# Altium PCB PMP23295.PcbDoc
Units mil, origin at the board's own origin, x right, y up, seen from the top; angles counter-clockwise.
Board outline 3149.61 x 1368.11 mil, 2 copper layers (Top Layer, Bottom Layer), stack 62 mil thick; 35 components, 23 nets, 88 pads, 2 vias.
Unrouted connection lines stored in the file: 14.
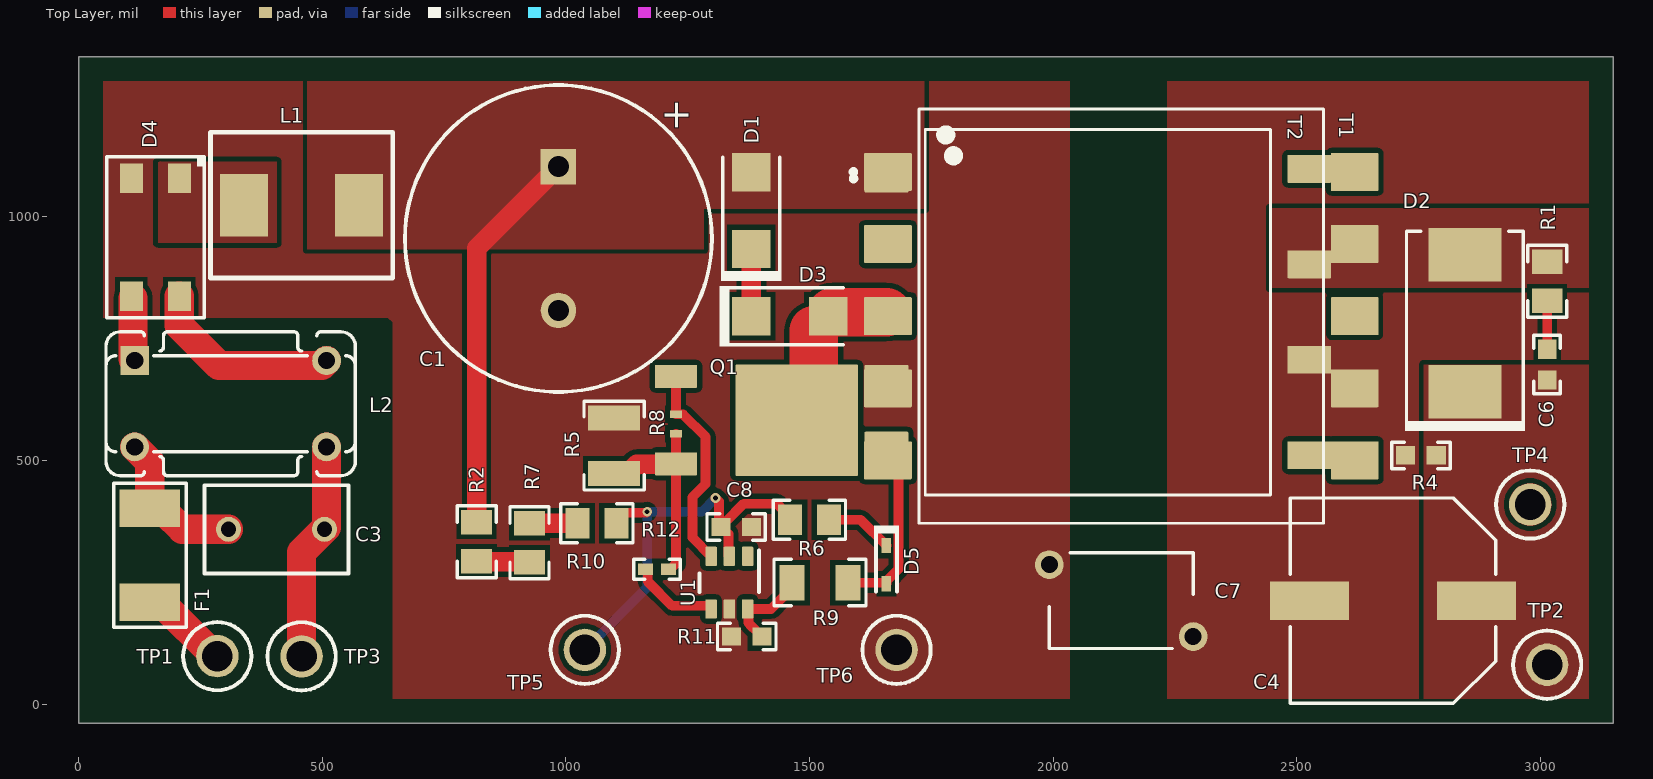
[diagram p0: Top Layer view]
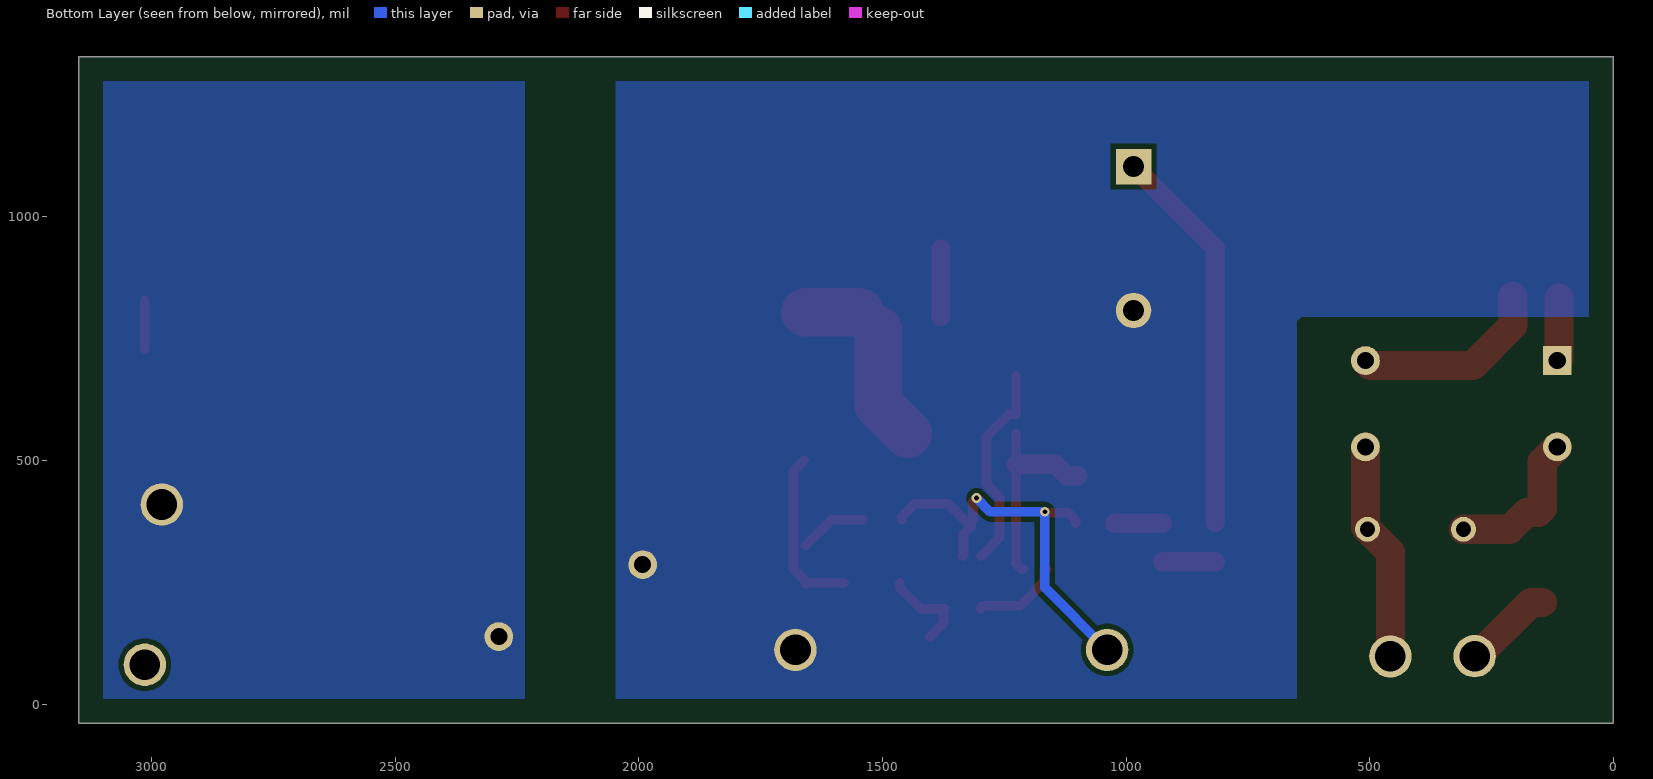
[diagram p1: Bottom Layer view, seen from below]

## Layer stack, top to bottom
Top Solder: solder mask 0.4, Solder Resist, Dk 3.5
Top Layer: signal copper 1.4
Dielectric1: core 59.2, FR-4 High Tg, Dk 4.8
Bottom Layer: signal copper 1.4
Bottom Solder: solder mask 0.4, Solder Resist, Dk 3.5

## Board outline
0,-39.37 3149.61,-39.37 3149.61,1328.74 0,1328.74

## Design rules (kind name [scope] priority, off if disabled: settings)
AcuteAngle [All] p1: minimum=4.50000000000000E+0001 checktracksonly=TRUE
AssemblyTestPointUsage [All] p1: valid=2
BoardOutlineClearance BoardOutlineClearance_MountingHoles [OnCopper and InComponentClass('Mounting Holes')] p1: gap=39.37 ignorepadtopadclearanceinfootprint=FALSE
BoardOutlineClearance BoardOutlineClearance_Poly [OnCopper and IsPoly] p2: gap=50 ignorepadtopadclearanceinfootprint=FALSE
BoardOutlineClearance [OnCopper and Not InComponentClass('Logo') and not InComponentClass('FiducialMark') and not InRegion(1000,500,4000,800) and not InPoly] p3: gap=75 ignorepadtopadclearanceinfootprint=FALSE
Clearance Clearance_Keepouts [((IsTrack Or IsArc) And Not InPoly) And IsFree and IsKeepOut vs ((IsTrack Or IsArc) And Not InPoly) And IsFree and IsKeepOut] p1: gap=0 ignorepadtopadclearanceinfootprint=FALSE
Clearance Clearance_Poly [InPolygon] p2: gap=10 ignorepadtopadclearanceinfootprint=TRUE
Clearance Clearance_FiducialMark [IsKeepOut and InComponentClass('FiducialMark') vs IsPad and InComponentClass('FiducialMark')] p3: gap=0 ignorepadtopadclearanceinfootprint=FALSE
Clearance [All] p4: gap=5 ignorepadtopadclearanceinfootprint=TRUE
ComponentClearance ComponentClearance_2 [InComponent('NT*')] p1: gap=0 collisioncheckmode=3 verticalgap=0 showdistances=FALSE
ComponentClearance ComponentClearance_MountingHoles_FiducialMarks [InComponentClass('Mounting Holes') vs InComponentClass('FiducialMark')] p2: gap=10 collisioncheckmode=3 verticalgap=10 showdistances=FALSE
ComponentClearance ComponentClearance_Shunt [InComponentClass('Header') vs InComponentClass('Shunt')] p3: gap=0 collisioncheckmode=3 verticalgap=0 showdistances=FALSE
ComponentClearance ComponentClearance_Logo [InComponentClass('Logo')] p4: gap=10 collisioncheckmode=3 verticalgap=10 showdistances=FALSE
ComponentClearance ComponentClearance_ScrewToNut [(HasFootprint('NY PMS 440 0025 PH')) vs (HasFootprint('Keystone_1902C'))] p5: gap=5 collisioncheckmode=3 verticalgap=10 showdistances=FALSE
ComponentClearance ComponentClearance_MountingHoles [InComponentClass('Mounting Holes')] p6: gap=10 collisioncheckmode=3 verticalgap=100000 showdistances=FALSE
ComponentClearance ComponentClearance_SmallPassives [HasFootprint('0201*') or HasFootprint('0402*') or HasFootprint('0508') or HasFootprint('0603*') or HasFootprint('0612') or HasFootprint('0805*') or HasFootprint('0815*') or HasFootprint('0830*') or HasFootprint('1206*') or HasFootprint('1210*') or HasFootprint('1808*') or HasFootprint('1812*') or HasFootprint('1825*') or HasFootprint('2010*') or HasFootprint('2220*') or HasFootprint('2225*') or HasFootprint('2512*') or HasFootprint('2728*') or HasFootprint('3518*') vs HasFootprint('0201*') or HasFootprint('0402*') or HasFootprint('0508') or HasFootprint('0603*') or HasFootprint('0612') or HasFootprint('0805*') or HasFootprint('0815*') or HasFootprint('0830*') or HasFootprint('1206*') or HasFootprint('1210*') or HasFootprint('1808*') or HasFootprint('1812*') or HasFootprint('1825*') or HasFootprint('2010*') or HasFootprint('2220*') or HasFootprint('2225*') or HasFootprint('2512*') or HasFootprint('2728*') or HasFootprint('3518*')] p7: gap=10 collisioncheckmode=3 verticalgap=10 showdistances=FALSE
ComponentClearance ComponentClearance_THtoSMT [IsThruComponent vs IsSMTComponent] p8: gap=10 collisioncheckmode=3 verticalgap=30 showdistances=FALSE
ComponentClearance ComponentClearance_THtoTH [IsThruComponent vs IsThruComponent] p9: gap=10 collisioncheckmode=3 verticalgap=30 showdistances=FALSE
ComponentClearance [All] p10: gap=10 collisioncheckmode=3 verticalgap=10 showdistances=FALSE
DiffPairsRouting [All] p1: maxlimit=100 minlimit=10 mostfreqgap=10 toplayer_minwidth=6 toplayer_maxwidth=15 toplayer_prefwidth=6 bottomlayer_minwidth=6 bottomlayer_maxwidth=15 bottomlayer_prefwidth=6 maxuncoupledlength=1000
FabricationTestPointUsage TestPointUsage [All] p1: valid=2 allowmultiple=FALSE
FabricationTestpoint Testpoint [All] p1: side=3 testpointundercomponent=TRUE minsize=40 maxsize=100 preferedsize=60 minholesize=0 maxholesize=40 preferedholesize=32 testpointgrid=1 allowsidetop=TRUE allowsidebottom=TRUE usegrid=TRUE gridtolerance=0.01
FanoutControl Fanout_LCC [IsLCC] p1: bgadir=Out bgaviamode=Centered fanoutstyle=Auto fanoutdirection=Alternating viagrid=1 // Fanout_LCC (Default Rule)
FanoutControl Fanout_BGA [IsBGA] p2: bgadir=Out bgaviamode=Centered fanoutstyle=Auto fanoutdirection=Alternating viagrid=1 // Fanout_BGA (Default Rule)
FanoutControl Fanout_Default [All] p4: bgadir=Out bgaviamode=Centered fanoutstyle=Auto fanoutdirection=Alternating viagrid=1 // Fanout_Default (Default Rule)
FanoutControl Fanout_Small [(CompPinCount < 5)] p5: bgadir=Out bgaviamode=Centered fanoutstyle=Auto fanoutdirection=OutThenIn viagrid=1 // Fanout_Small (Default Rule)
Height [All] p1: minheight=0 maxheight=1100 prefheight=500
HoleSize [All] p1: absolutevalues=TRUE maxlimit=270 minlimit=7.87 maxpercent=80.000 minpercent=20.000
HoleToHoleClearance [All] p1: gap=5 allowstackedmicrovias=TRUE
MinimumAnnularRing MinimumAnnularRing_ThermalPadVias [IsVia and InAnyComponent] p1: minimumring=4
MinimumAnnularRing [All] p2: minimumring=4
MinimumSolderMaskSliver MinimumSolderMaskSliver_Logo [InComponentClass('Logo') vs InComponentClass('Logo')] p1: minsoldermaskwidth=0.7
MinimumSolderMaskSliver [All] p2: minsoldermaskwidth=1.5
PlaneClearance [All] p1: clearance=5
PlaneConnect [All] p1: planeconnectstyle=Relief reliefexpansion=10 reliefentries=4 reliefconductorwidth=10 reliefairgap=10
PolygonConnect [All] p1: connectstyle=Direct reliefconductorwidth=10 reliefentries=4 polygonreliefangle="90 Angle" airgapwidth=10
RoutingVias ThermalPadVias [IsVia and InAnyComponent] p1: holewidth=7.87 width=19.68 viastyle="Through Hole" minholewidth=7.87 minwidth=19.68 maxholewidth=12.99 maxwidth=23.62
RoutingVias [All] p2: holewidth=10 width=18 viastyle="Through Hole" minholewidth=4 minwidth=15 maxholewidth=40 maxwidth=64
SMDEntry [All] p1 off: side=TRUE corner=TRUE anyangle=FALSE
SMDToCorner [All] p1 off: distance=50000
SilkToBoardRegionClearance [Not ((IsComment or IsDesignator) And (Hide <> 'False')) and not InRegion(1000,500,4000,800)] p1:
SilkToSilkClearance SilkToSilkClearance_Pb-FreeLogo [(HasFootprint('Pb-Free_Overlay_Medium') OR HasFootprint('Pb-Free_Overlay_Small')) vs (HasFootprint('Pb-Free_Overlay_Medium') OR HasFootprint('Pb-Free_Overlay_Small'))] p1: silktosilkclearance=0
SilkToSilkClearance [All] p2: silktosilkclearance=0
SilkToSolderMaskClearance SilkToComponentPadClearance [(IsPad or IsFill or IsRegion) and InAnycomponent] p1: minsilkscreentomaskgap=3 clearancetoexposedcopper=TRUE
SilkToSolderMaskClearance "Silk to Solder Mask Opening" [All] p2: minsilkscreentomaskgap=3.94 clearancetoexposedcopper=FALSE
SolderMaskExpansion [All] p1: expansion=4 istentingtop=FALSE
UnRoutedNet [All] p1: checkbadconnections=TRUE
Width [All] p1: maxlimit=100 minlimit=5 preferedwidth=10 checkconnectedcopper=TRUE
11 further rules are at their usual default settings.

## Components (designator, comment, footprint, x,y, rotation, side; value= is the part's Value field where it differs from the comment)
C1 "EEUED2D151" CAPPR7.5-16x25 984.54,955.63 r270 top value=150uF
C3 "R82IC3100DQ60J" R82_720x450x950 405.9,358.83 r0 top value=0.1uF
C4 "EEE-FC1H101P" SM_RADIAL_G 2697.56,212.41 r180 top value=100uF
C6 "06031C102MAT2A" 0603 3014.01,696.77 r90 top value=1000pF
C7 "VY2471K29Y5SS63V7" VY2_750x500 2139.82,212.42 r180 top value=470pF
C8 "C1608X5R1H105K080AB" 0603 1349.44,363.7 r0 top value=1uF
D1 "SMAJ150A" SMA 1380.63,1012.84 r90 top value=150V
D2 "CDBC5200-HF" SMC 2845.19,781.77 r90 top value=200V
D3 "US1G-13-F" SMA 1459.37,796.3 r0 top value=400V
D4 "HD02-T" MiniDIP 157.2,958.27 r270 top value=200V
D5 "1N4148WT" Fairchild_SOD-523F 1657.72,286.24 r270 top value=75V
F1 "045201.5MRL" SloBlo452 145.54,305.48 r270 top
L1 "DR74-101-R" DR74 457.4,1024.21 r0 top value=100uH
L2 "744821201" WE-CMB_XS 311.73,616.51 r0 top value=1mH
Q1 "SPD03N60S5XT" FP-IPD50R2K0CEAUMA1_PG-TO252-3-MFG 1427.53,582.79 r270 top
R1 "RP73PF2A1K0BTDF" 0805_HV 3014.01,868.22 r270 top value=1.00k
R2 "CRCW08051M00JNEA" 0805_HV 816.54,333.01 r90 top value=1.0Meg
R4 "RCA06031K00JNEA" 0603 2754.95,510.61 r0 top value=1.0k
R5 "MCR25JZHFLR150" 1210 1098.77,530.61 r270 top value=0.15
R6 "RC0805FR-0710RL" 0805_HV 1499.82,378.47 r180 top value=10.0
R7 "CRCW08051M00JNEA" 0805_HV 925.2,331.3 r270 top value=1.0Meg
R8 "MCS0402MD1002BE100" 0402S 1225.76,574.91 r90 top value=10.0k
R9 "ERJ-8ENF4873V" 1206 1521.42,249.32 r0 top value=487k
R10 "CRCW0402110RFKED" 0402 1186.87,277.06 r0 top value=110
R11 "RT0603BRD07182KL" 0603 1371.09,138.52 r0 top value=182k
R12 "CRCW08051M00JNEA" 0805_HV 1063.7,371.3 r180 top value=1.0Meg
T1 "RLTI-1453" FP-RLTI-1453_SMT10_0IN85_0IN80-MFG 2139.82,796.3 r0 top
T2 "RLTI-1452" FP-RLTI-1452_SMT9_0IN75_0IN93-MFG 2091.72,804.61 r0 top
TP1 "5012" Keystone5012 284.35,98.43 r0 top
TP2 "5010" Keystone5010 3014.01,80.82 r90 top
TP3 "5011" Keystone5011 457.4,97.98 r0 top
TP4 "5011" Keystone5011 2979.21,409.64 r90 top
TP5 "5010" Keystone5010 1038.67,111.32 r180 top
TP6 "5011" Keystone5011 1678.62,111.32 r270 top
U1 "UCC28704DBVR-1" DBV0006A_N 1335.42,249.32 r270 top

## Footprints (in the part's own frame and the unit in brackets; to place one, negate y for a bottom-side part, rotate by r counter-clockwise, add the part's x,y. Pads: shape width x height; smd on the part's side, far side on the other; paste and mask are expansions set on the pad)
0402 [mm] "0402 from SM-752 data"
  rect 0.8x0.6 smd: 1(-0.6,0) 2(0.6,0)
  silkscreen extent -1.22,-0.52 1.22,0.52, body extent -0.55,-0.3 0.55,0.3, height 0.6
0402S [mil] "Based on C0402S footprint from PADS legacy"
  rect 15x24 smd: 1(-20,0) 2(20,0)
  body extent -22,-12 22,12, height 24
0603 [mm] "0603 from SM-752 data"
  rect 1x0.95 smd: 1(-0.8,0) 2(0.8,0)
  silkscreen extent -1.52,-0.69 1.52,0.69, body extent -0.87,-0.47 0.87,0.47, height 1
0805_HV [mil] "0805 with 30mil clearance between pads"
  rect 50x63 smd: 1(-40,0) 2(40,0)
  silkscreen extent -74,-40 74,40, body extent -43,-29 43,29, height 57
1206 [mm] "1206 from SM-752 data"
  rect 1.3x1.85 smd: 1(-1.45,0) 2(1.45,0)
  silkscreen extent -2.4,-1.21 2.4,1.21, body extent -1.7,-0.9 1.7,0.9, height 1.35
1210 [mm] "1210 from SM-752 data"
  rect 1.3x2.7 smd: 1(-1.45,0) 2(1.45,0)
  silkscreen extent -2.32,-1.57 2.32,1.57, body extent -1.7,-1.35 1.7,1.35, height 1.35
CAPPR7.5-16x25 [mm] "Capacitor, Electrolytic, Radial; Body 16 x 25 mm (Dia.xH typ); Pin Spacing 7.5 mm (typ)"
  rect 1.85x1.85 hole 1.1: 1(-3.75,0)
  round 1.85 hole 1.1: 2(3.75,0)
  silkscreen extent -8,-8 8,8, body extent -8,-8.01 8,8.01, height 27
DBV0006A_N [mm] "SOT23, 6-Leads, Body 2.9x1.6mm, Pitch 0.95mm, Lead Span 2.8mm, IPC Medium Density"
  rrect17% 1x0.6 smd: 1(-1.375,0.95) 2(-1.375,0) 3(-1.375,-0.95) 4(1.375,-0.95) 5(1.375,0) 6(1.375,0.95)
  silkscreen extent -1.68,-1.55 0.5,1.55, body extent -1.42,-1.46 1.42,1.46, height 1.12
DR74 [mm]
  rect 2.5x3.25 smd: 1(-3,0) 2(3,0)
  silkscreen extent -4.75,-3.8 4.75,3.8, body extent -3.8,-3.8 3.8,3.8, height 4.35
Fairchild_SOD-523F [mm] "SMD, 2-Leads, Body 1.2x0.8mm"
  rect 0.8x0.5 smd: 1(-1,0) 2(1,0)
  silkscreen extent -2.03,-0.65 1.4,0.65, body extent -0.65,-0.45 0.65,0.45, height 0.7
FP-IPD50R2K0CEAUMA1_PG-TO252-3-MFG [mm]
  rrect8% 1.2x2.2 smd paste-1000 mask+0: 1(-2.28,-5.125) 3(2.28,-5.125)
  rrect2% 5.8x6.4 smd paste-1000 mask+0: 4(0,1.175)
  body extent -3.3,-5.95 3.3,4.15, height 2.55
FP-RLTI-1452_SMT9_0IN75_0IN93-MFG [mil]
  rrect7% 90x57 smd paste+0 mask+0: 1(-434,274) 2(-434,137) 3(-434,0) 4(-434,-137) 5(-434,-274) 6(434,-294) 7(434,-98) 8(434,98) 9(434,294)
  silkscreen extent -506,-375 354,375, body extent -483,-379 483,379, height 10
FP-RLTI-1453_SMT10_0IN85_0IN80-MFG [mil]
  rrect5% 98x78 smd paste+0 mask+0: 1(-479,296) 2(-479,148) 3(-479,0) 4(-479,-148) 5(-479,-296) 6(479,-296) 7(479,-148) 8(479,0) 9(479,148) 10(479,296)
  silkscreen extent -555,-425 415,425, body extent -532,-429 532,429, height 10
Keystone5010 [mil] "Keystone Multipurpose loops"
  round 87 hole 63: 1(0,0)
  silkscreen extent -70,-70 70,70, body extent -63,-63 63,62, height 319
Keystone5011 [mil] "Keystone Multipurpose loops"
  round 87 hole 63: 1(0,0)
  silkscreen extent -70,-70 70,70, body extent -63,-63 63,62, height 319
Keystone5012 [mil] "Keystone Multipurpose loops"
  round 87 hole 63: 1(0,0)
  silkscreen extent -70,-70 70,70, body extent -63,-63 63,62, height 319
MiniDIP [mm] "Land pattern created based on STEP model."
  rect 1.52x1.2 smd: 1(-3.075,1.25) 2(-3.075,-1.25) 3(3.075,-1.25) 4(3.075,1.25)
  silkscreen extent -4.19,-2.54 4.19,2.54, body extent -3.5,-2.45 3.5,2.45, height 2.75
R82_720x450x950 [mm] "TH, 2-Leads, Body 7.2x4.5mm, Pin Spacing 5mm"
  round 1.3 hole 0.8: 1(-2.5,0) 2(2.5,0)
  silkscreen extent -3.75,-2.3 3.75,2.3, body extent -3.75,-2.3 3.75,2.3, height 9.6
SloBlo452 [mm] "Littelfuse 452/4 Fuses, recommended land pattern"
  rect 1.96x3.15 smd: 1(-2.455,0) 2(2.455,0)
  silkscreen extent -3.75,-1.88 3.75,1.9, body extent -3.05,-1.35 3.05,1.34, height 2.69
SM_RADIAL_G [mm] "10 x 10.2mm:  Panasonic G"
  rect 4.1x2 smd: 1(-4.35,0) 2(4.35,0)
  silkscreen extent -5.35,-5.35 5.35,5.35, body extent -5.25,-5.25 5.25,5.25, height 10.5
SMA [mm] "Molded Diode, 2-Leads, Body 4.3x2.6mm, IPC Medium Density, based on OnSemi component dimensions and land pattern"
  rect 2x2 smd: 1(-2,0) 2(2,0)
  silkscreen extent -3.66,-1.57 2.79,1.58, body extent -2.6,-1.3 2.6,1.3, height 2.42
SMC [mil] "Molded Diode, 2-Leads, Body 6.9x5.8mm, IPC Medium Density, based on OnSemi component dimensions and land patterns"
  rect 110x150 smd: 1(-140.49,0) 2(140.49,0)
  silkscreen extent -221,-123 189,124, body extent -156,-116 156,116, height 91
VY2_750x500 [mm] "Vishay"
  round 1.5 hole 0.889: 1(-3.75,1.875) 2(3.75,-1.875)
  silkscreen extent -3.75,-2.5 3.75,2.5, body extent -4.05,-2.5 4.05,2.5, height 10.49
WE-CMB_XS [mm] "WE-CMB Series Size XS"
  rect 1.5x1.5 hole 0.9: 1(-5,2.25)
  round 1.5 hole 0.9: 2(-5,-2.25) 3(5,-2.25) 4(5,2.25)
  silkscreen extent -6.5,-3.75 6.5,3.75, body extent -6.5,-3.75 6.5,3.75, height 16.24

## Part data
C1: library part CMP-0010012-2, "CAP, AL, 150 uF, 200 V, +/- 20%, 0.16247 ohm, TH", AC_Derating=0.35, Manufacturer=Panasonic, Supplier Part Number 1=P13520-ND, Tolerance_%=20%, Value1="0.16247 ohm", Value2=200V, ValueDisplayed=150uF
C3: library part CMP-0012568-2, "CAP, Film, 0.1 uF, 250 V, +/- 5%, TH", Cap_Case=7.2x4.5x9.5mm, Manufacturer=Kemet, Supplier Part Number 1=399-5456-1-ND, Tolerance_%=5%, Value1=Unknown, Value2=250V, ValueDisplayed=0.1uF
C4: library part CMP-0011166-1, "CAP, AL, 100 uF, 50 V, +/- 20%, 0.3 ohm, SMD", Cap_Case=G, Manufacturer=Panasonic, Supplier Part Number 1=PCE4013CT-ND, Tolerance_%=20%, Value1="0.3 ohm", Value2=50V, ValueDisplayed=100uF
C6: library part CMP-0006725-3, "CAP, CERM, 1000 pF, 100 V, +/- 20%, X7R, 0603", Cap_Case=0603, Manufacturer=AVX, Supplier Part Number 1=478-3699-1-ND, TempCo=X7R, Tolerance_%=20%, Value1="0.276 ohm", Value2=100V, ValueDisplayed=1000pF
C7: library part CMP-0009629-1, "CAP, CERM, 470 pF, 300 V, +/- 10%, VY2, 5x7.5 mm", Cap_Case="Disk, 5x7.5 mm", Manufacturer=Vishay-Bccomponents, Supplier Part Number 1=BC2352-ND, TempCo=VY2, Tolerance_%=10%, Value1=Unknown, Value2=300V, ValueDisplayed=470pF
C8: library part CMP-0007011-2, "CAP, CERM, 1 uF, 50 V, +/- 10%, X5R, 0603", Cap_Case=0603, Manufacturer=TDK, Supplier Part Number 1=445-7468-1-ND, TempCo=X5R, Tolerance_%=10%, Value1="0.005522 ohm", Value2=50V, ValueDisplayed=1uF
D1: library part CMP-0084982-1, "Diode, TVS, Uni, 150 V, 243 Vc, 400 W, 1.6 A, SMA", Manufacturer=Littelfuse, Value1=243V
D2: library part CMP-0077804-2, "Diode, Schottky, 200 V, 5 A, SMC", Manufacturer="Comchip Technology", Value1=5A, Value2=0.9V
D3: library part CMP-0077026-1, "Diode, Ultrafast, 400 V, 1 A, SMA", Manufacturer="Diodes Inc.", Supplier Part Number 1=US1G-FDICT-ND, Value1=1A, Value2=1.3V
D4: library part CMP-0029216-2, "Diode, Switching-Bridge, 200 V, 0.8 A, MiniDIP", Manufacturer="Diodes Inc.", Supplier Part Number 1=HD02DICT-ND, Value1=0.8A, Value2=1V
D5: library part CMP-0076982-2, "Diode, Switching, 75 V, 0.3 A, SOD-523F", Manufacturer="Fairchild Semiconductor", Value1=0.3A, Value2=V
F1: library part CMP-0003477-2, "Fuse, 1.5 A, 125VAC/VDC, SMD", Irating_A=1.5A, Manufacturer=Littelfuse, Supplier Part Number 1=F2601CT-ND
L1: library part CMP-0058224-1, "Inductor, Shielded Drum Core, Ferrite, 100 uH, 0.86 A, 0.383 ohm, SMD", Manufacturer=Coiltronics, Supplier Part Number 1=513-1225-1-ND, Value1="0.383 ohm", Value2=0.86A, ValueDisplayed=100uH
L2: library part CMP-0013113-1, "Coupled inductor, 1 mH, 2 A, 0.045 ohm, TH", Manufacturer="Wurth Elektronik", Supplier Part Number 1=732-1435-ND, ValueDisplayed=1mH
Q1: library part CMP-0086470-1, "MOSFET N-CH 500V 2.4A PG-TO252", Manufacturer=Infineon, PartNumber=IPD50R2K0CEAUMA1
R1: library part CMP-0019089-1, "RES, 1.00 k, 0.1%, 0.25 W, 0805", Manufacturer="TE Connectivity", Power_W=250mW, Supplier Part Number 1=A110543CT-ND, TempCo="25 ppm/C", Tolerance_%=0.1%, Value2=0.25W, Value_Code=1k00, ValueDisplayed=1.00k
R2 R7 R12: library part CMP-0020480-2, "RES, 1.0 M, 5%, 0.125 W, 0805", Manufacturer=Vishay-Dale, Power_W=125mW, Supplier Part Number 1=541-1.0MACT-ND, TempCo="200 ppm/C", Tolerance_%=5%, Value2=0.125W, Value_Code=1M00, ValueDisplayed=1.0M
R4: library part CMP-0025946-1, "RES, 1.0 k, 5%, 0.1 W, AEC-Q200 Grade 0, 0603", Manufacturer=Vishay-Dale, Power_W=100mW, Supplier Part Number 1=541-2213-1-ND, TempCo="200 ppm/C", Tolerance_%=5%, Value2=0.1W, Value_Code=1k00, ValueDisplayed=1.0k
R5: library part CMP-0015171-2, "RES, 0.15, 1%, 0.5 W, 1210", Manufacturer=Rohm, Power_W=500mW, Supplier Part Number 1=RHM.15SCT-ND, TempCo="200 ppm/C", Tolerance_%=1%, Value2=0.5W, Value_Code=R150, ValueDisplayed=0.15
R6: library part CMP-0021863-1, "RES, 10.0, 1%, 0.125 W, 0805", Manufacturer="Yageo America", Power_W=125mW, Supplier Part Number 1=311-10.0CRCT-ND, TempCo="200 ppm/C", Tolerance_%=1%, Value2=0.125W, Value_Code=10R0, ValueDisplayed=10.0
R8: library part CMP-0077124-1, "RES, 10.0 k, 0.1%, 0.1 W, AEC-Q200 Grade 0, 0402", Manufacturer=Vishay/Beyschlag, Power_W=100mW, Supplier Part Number 1=MCS0402-10.0K-MBCT-ND, TempCo="25 ppm/C", Tolerance_%=0.1%, Value2=0.1W, Value_Code=10k0, ValueDisplayed=10.0k
R9: library part CMP-0017626-1, "RES, 487 k, 1%, 0.25 W, 1206", Manufacturer=Panasonic, Power_W=250mW, Supplier Part Number 1=P487KFCT-ND, TempCo="100 ppm/C", Tolerance_%=1%, Value2=0.25W, Value_Code=487k
R10: library part CMP-0025968-2, "RES, 110, 1%, 0.063 W, 0402", Manufacturer=Vishay-Dale, Power_W=63mW, Supplier Part Number 1=541-110LCT-ND, TempCo="100 ppm/C", Tolerance_%=1%, Value2=0.063W, Value_Code=110R, ValueDisplayed=110
R11: library part CMP-0023828-3, "RES, 182 k, 0.1%, 0.1 W, 0603", Manufacturer="Yageo America", Power_W=100mW, TempCo="25 ppm/C", Tolerance_%=0.1%, Value2=0.1W, Value_Code=182k
T1: library part CMP-0096939-1, "Transformer Flyback (EFD20) for PMP23925", Manufacturer="Renco Electronics", Operating Temperature Range=to, Voltage_Isolation_Vrms=1.5kV
T2: library part CMP-0096938-1, "Transformer Flyback (EPC17) for PMP23925", Manufacturer="Renco Electronics", Operating Temperature Range=to, Voltage_Isolation_Vrms=1.5kV
TP1: library part CMP-0055149-1, "Test Point, Multipurpose, White, TH", Color=White, Manufacturer=Keystone, Supplier Part Number 1=36-5012-ND
TP2 TP5: library part CMP-0055147-1, "Test Point, Multipurpose, Red, TH", Color=Red, Manufacturer=Keystone, Supplier Part Number 1=36-5010-ND
TP3 TP4 TP6: library part CMP-0055148-1, "Test Point, Multipurpose, Black, TH", Color=Black, Manufacturer=Keystone, Supplier Part Number 1=36-5011-ND
U1: library part CMP-0074087-1, "Off-Line Constant-Voltage Constant-Current Flyback Controller With Primary-Side Regulation (PSR), DBV0006A (SOT-23-6)", Alternate Manufacturer="Texas Instruments", Alternate PartNumber=UCC28704DBVT-1

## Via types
v1: diameter 20, hole 10, Top Layer to Bottom Layer, 2 vias

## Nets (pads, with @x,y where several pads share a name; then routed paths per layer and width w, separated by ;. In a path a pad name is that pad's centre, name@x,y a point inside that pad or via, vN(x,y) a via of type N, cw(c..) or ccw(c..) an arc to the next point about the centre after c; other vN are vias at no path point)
33V: C4.1 C6.1 D2.1 R4.2 TP2.1
132VAC: F1.2 TP1.1 | length 184.5
  Top Layer w60: F1.2 168.97,208.82 279.37,98.43 TP1.1
NetC3_1: C3.1 F1.1 L2.2 | length 318.4
  Top Layer w60: L2.2 145.54,497.26 F1.1 154.13,393.55 177.55,393.55 212.27,358.83 C3.1
NetC6_2: C6.2 R1.2 | length 100
  Top Layer w20: C6.2 R1.2
NetD1_1: D1.1 D3.1 | length 137.8
  Top Layer w40: D3.1 D1.1
NetD4_1: D4.1 L1.1
NetD4_3: D4.3 L2.1 | length 135
  Top Layer w20: D4.3 D4.3@111.43,833.76 ; L2.1@111.43,708.54 L2.1
  Top Layer w60: L2.1@111.43,708.54 D4.3@111.43,833.76
NetD4_4: D4.4 L2.4 | length 400.3
  Top Layer w60: D4.4 206.41,776.95 288.1,695.25 498.74,695.25 L2.4
NetD5_1: D5.1 R6.1 | length 139.8
  Top Layer w20: R6.1 1604.86,378.47 D5.1
NetQ1_1: Q1.1 R8.2 U1.3 | length 430.1
  Top Layer w20: Q1.1 R8.2 1240.62,594.91 1286.66,548.88 1286.66,451.87 1259.66,424.87 1259.66,341.82 U1.3
NetQ1_3: Q1.3 R5.2 R8.1 R10.2 | length 423.5
  Top Layer w20: R10.2 1214.43,277.06 1225.76,288.4 Q1.3 ; Q1.3@1225.5,492.76 Q1.3 ; R8.1 Q1.3
  Top Layer w40: R5.2@1098.77,468.88 1121.68,468.88 1145.57,492.76 Q1.3@1225.5,492.76
NetR2_1: R2.1 R7.2 | length 109.4
  Top Layer w20: R2.1 R2.1@817.39,292.15 ; R7.2@924.34,292.15 R7.2
  Top Layer w40: R2.1@817.39,292.15 R7.2@924.34,292.15
NetR7_1: R7.1 R12.2 | length 98.5
  Top Layer w40: R7.1 R12.2
NetR9_1: R9.1 R11.2 U1.6 | length 189.8
  Top Layer w20: R11.2 1401.61,138.52 1392.91,147.22 1392.91,148.21 1377.16,163.96 1377.16,164.63 1374.64,167.15 1374.64,193.38 U1.6 1421.02,195.19 1464.33,238.49 R9.1
NetR10_1: R10.1 U1.4 | length 185.2
  Top Layer w20: R10.1 1166.08,277.06 1167.89,275.25 1167.89,251.72 1217.93,201.68 1296.21,201.68 1298.02,199.87 U1.4
Neutral: C3.2 L2.3 TP3.1 | length 451.2
  Top Layer w60: TP3.1 457.4,311.9 C3.2 508.58,363.08 L2.3
OUT: D2.2 R1.1 T1.9 T2.8
PGND: C1.2 C7.2 C8.2 D4.2 R5.1 R11.1 T1.4 T2.4 TP6.1 U1.5
RTN: C4.2 C7.1 R4.1 T1.7 T2.7 TP4.1
V_AUX: D5.2 R9.2 T1.5 T2.5 | length 352.1
  Top Layer w20: R9.2 1657.56,249.32 D5.2@1657.72,249.16 ; D5.2 D5.2@1657.72,249.16 ; T1.5 1682.72,478.4 1682.72,277.46 1657.72,252.46 D5.2@1657.72,249.16
V_BULK: C1.1 D1.2 L1.2 R2.2 T1.1 T2.1 | length 799.9
  Top Layer w40: R2.2 816.54,935.26 C1.1
V_DRAIN: D3.2 Q1.4 T1.3 T2.3 | length 401.7
  Top Layer w20: D3.2@1508.74,766.93 D3.2 D3.2@1546.42,804.61
  Top Layer w100: Q1.4@1448.2,554.91 1508.74,615.45 D3.2@1508.74,766.93 ; D3.2@1546.42,804.61 T2.3
VDD: C8.1 R6.2 R12.1 TP5.1 U1.2 | length 861.7
  Top Layer w20: R12.1 1103.7,377.8 1118.7,392.8 1164.68,392.8 v1(1166.66,394.78) ; v1(1306.94,422.9) 1313.89,415.95 1313.89,378.12 1317.94,374.06 C8.1 1318.93,363.7 1333.61,349.02 1333.61,305.27 U1.2 ; C8.1@1327.63,374.06 1364.87,411.3 1433.49,411.3 1459.82,384.97 R6.2
  Bottom Layer w20: TP5.1 1166.66,239.31 v1(1166.66,394.78) 1278.82,394.78 v1(1306.94,422.9)
pads on no net: T1.2 T1.6 T1.8 T1.10 T2.2 T2.6 T2.9 U1.1

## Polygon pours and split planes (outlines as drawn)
PGND on Top Layer "TOP_LAYER_PGND_P017" (solid, remove dead copper, pour order 17): 0,1328.74 0,793.27 634.44,793.27 644.41,783.3 644.41,-39.37 2034.5,-39.37 2034.5,1328.74
V_BULK on Top Layer "TOP_LAYER_V_BULK_P000" (solid, remove dead copper, pour order 0): 469.47,934.1 1282.75,934.1 1282.75,1011.02 1282.75,1016.99 1735.93,1016.99 1735.93,1214.09 1735.93,1307.97 469.47,1299.21
NetD4_1 on Top Layer "TOP_LAYER_NETD4_1_P009" (solid, pour order 9): 162.79,1118.42 162.79,946.96 405.9,946.96 405.9,1112.87 168.34,1112.87
OUT on Top Layer "TOP_LAYER_OUT_P012" (solid, pour order 12): 3114.98,858.38 3111.4,854.8 2446.05,854.8 2446.05,1017.67 3114.98,1017.67
RTN on Top Layer "TOP_LAYER_RTN_P014" (solid, pour order 14): 2234.25,9.84 2234.25,1328.74 3149.61,1328.74 3149.61,9.84 2244.09,9.84
33V on Top Layer "TOP_LAYER_33V_P011" (solid, pour order 11): 2760.85,696.77 2760.85,-45.92 3130.63,-45.92 3130.63,696.77
PGND on Bottom Layer "BOTTOM_LAYER_PGND_P018" (solid, remove dead copper, pour order 18): 5.2,1330.79 5.2,795.32 639.64,795.32 649.61,785.35 649.61,-37.32 2047.24,-37.32 2047.24,1330.79
RTN on Bottom Layer "BOTTOM_LAYER_RTN_P013" (solid, pour order 13): 2234.25,9.84 2234.25,1328.74 3149.61,1328.74 3149.61,9.84 2244.09,9.84

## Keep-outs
Keep-Out Layer:
  text ".Layer_Name" at 577,-858.49 h60

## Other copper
Top Layer:
  text ".Layer_Name" at 577,-858.49 h60
Bottom Layer:
  text ".Layer_Name" at 577,-858.49 h60

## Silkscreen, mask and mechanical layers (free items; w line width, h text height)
Top Overlay:
  text ".Layer_Name" at 577,-858.49 h60
Bottom Overlay:
  text ".Layer_Name" at 577,-858.49 h60
Top Paste:
  text ".Layer_Name" at 577,-858.49 h60
Bottom Paste:
  text ".Layer_Name" at 577,-858.49 h60
Top Solder:
  text ".Layer_Name" at 577,-858.49 h60
  text ".Layer_Name" at 577,-858.49 h60
Bottom Solder:
  text ".Layer_Name" at 577,-858.49 h60
Drill Guide:
  text ".Layer_Name" at 577,-858.49 h60
M1 Board Outline:
  lines w10: 3148.99,1328.74 357.14,1328.74 0,1328.74 0,-39.37 3149.61,-39.37 3149.61,1328.74
  text ".Layer_Name" at 577,-858.49 h60
M2 Board Dimensions:
  rectangle: 0,-275 125,-150
  rectangle: 125,-400 500,-275
  lines w7: 0,-275 1000,-275 ; 125,-400 125,-150 ; 250,-400 250,-150 ; 500,-400 500,-150 ; 750,-400 750,-150 ; 0,-400 1000,-400 1000,-150 0,-150 0,-400
  text ".Layer_Name" at 577,-858.49 h60
M3 3D STEP Top:
  text ".Layer_Name" at 577,-858.49 h60
M4 3D STEP Bottom:
  text ".Layer_Name" at 577,-858.49 h60
M5 Assembly Top:
  lines w10: -292,-930.17 6308,-930.17 ; -292,-726.83 6310,-726.83 ; -292,-523.5 -292,-1133.5 3713,-1133.5 6310,-1133.5 6310,-523.5 -291.5,-523.5 -291.5,-1133.5 1284,-1133.5 ; 2173,-1133.5 2173,-523.5 ; 3440,-726.83 3440,-523.5 ; 4280,-726.83 4280,-523.5 ; 4902,-1140 4902,-937.17
  text "COMPONENTS MARKED 'DNP' SHOULD NOT BE POPULATED." at 1153.5,-318.5 h60
  text "ASSEMBLY VARIANT:" at 1153,-434 h60
  text ".VariantName" at 2189,-434 h60
  text "PCB VIEWED FROM TOP SIDE" at -228.5,-655.67 h60
  text "BOARD #:" at 2248,-655.67 h60
  text ".PRJ_Number" at 2793.5,-655.67 h60
  text "REV:" at 3638,-655.67 h60
  text ".PCB_Rev" at 3929.5,-655.67 h60
  text "SVN REV:" at 4476,-655.67 h60
  text ".VersionControl_RevNumber" at 4982,-655.67 h60
  text "TID #:" at 2248,-859 h60
  text ".TID" at 2793.5,-859 h60
  text "PLOT NAME =" at -228.5,-1064.34 h60
  text ".plot_File_Name" at 577,-1064.34 h60
  text "GENERATED    :" at 2250,-1064.34 h60
  text ".Print_Date" at 3119.5,-1064.34 h60
  text ".Print_Time" at 3848.5,-1064.34 h60
  text "TEXAS INSTRUMENTS" at 5113,-1064.34 h60
M6 Assembly Bottom:
  lines w10: -292.5,-727.33 6309.5,-727.33 ; -290.5,-930.67 6309.5,-930.67 ; 1115.5,-1140.5 1115.5,-937.67 ; 1737.5,-727.33 1737.5,-524 ; 2577.5,-727.33 2577.5,-524 ; 3844.5,-1134 3844.5,-524 ; 4733.5,-1134 6309,-1134 6309,-524 -292.5,-524 -292.5,-1134 2304.5,-1134 6309.5,-1134 6309.5,-524
  text "COMPONENTS MARKED 'DNP' SHOULD NOT BE POPULATED." at 6102,-318 h60
  text ".VariantName" at 5058,-434 h60
  text "ASSEMBLY VARIANT:" at 6097,-434 h60
  text ".VersionControl_RevNumber" at 1035.5,-656.17 h60
  text "SVN REV:" at 1541.5,-656.17 h60
  text ".PCB_Rev" at 2088,-656.17 h60
  text "REV:" at 2379.5,-656.17 h60
  text ".PRJ_Number" at 3224,-656.17 h60
  text "BOARD #:" at 3769.5,-656.17 h60
  text "PCB VIEWED FROM BOTTOM SIDE" at 6246,-656.17 h60
  text ".TID" at 3224,-859.5 h60
  text "TID #:" at 3769.5,-859.5 h60
  text "TEXAS INSTRUMENTS" at 904.5,-1064.84 h60
  text ".Print_Time" at 2169,-1064.84 h60
  text ".Print_Date" at 2898,-1064.84 h60
  text "GENERATED    :" at 3767.5,-1064.84 h60
  text ".plot_File_Name" at 5440.5,-1064.84 h60
  text "PLOT NAME =" at 6246,-1064.84 h60
M9 Title Sheet:
  drawing of 57 lines, arcs and shapes, not listed
  text "1" at 739.84,8036.5 h70
  text "2" at 3235.5,8036.5 h70
  text "3" at 5724.84,8036.5 h70
  text "4" at 8231.51,8036.5 h70
  text "5" at 10730.5,8036.5 h70
  text "6" at 13235.5,8036.5 h70
  text "A" at -416.5,6893.5 h70
  text "A" at 14383.5,6893.5 h70
  text "B" at -416.5,4513.5 h70
  text "B" at 14383.5,4513.5 h70
  text "C" at -416.5,2138.5 h70
  text "C" at 14383.5,2138.5 h70
  text "PROJECT TITLE:" at 11343.5,277.5 h45
  text ".PRJ_Title" at 11393.5,144.17 h70
  text "DESIGNED FOR:" at 11343.5,-23.5 h45
  text ".PRJ_Customer" at 11393.5,-163.5 h70
  text "D" at -416.5,-231.5 h70
  text "D" at 14383.5,-231.5 h70
  text "FILE NAME:" at 11343.5,-323.5 h45
  text ".PCB_File_Name_No_Path" at 11393.5,-443.5 h70
  text "Texas Instruments (TI) and/or its licensors do not warrant the accuracy or completeness of this specification" at 6374,-605.34 h45
  text "ENGINEER:" at 11343.5,-613.5 h45
  text "LAYOUT BY:" at 12848.5,-613.5 h45
  text "or any information contained therein. TI and/or its licensors do not warrant that this design will meet" at 6329.01,-718 h45
  text ".PRJ_Engineer" at 11393.5,-768.49 h70
  text ".PCB_Layout" at 12899,-768.49 h70
  text "the specifications, will be suitable for your application or fit for any particular purpose, or will operate in" at 6329.01,-830.67 h45
  text ".Layer_Name" at 577,-858.49 h60
  text "ALTIUM DESIGNER VERSION:" at 12848.5,-923.5 h45
  text "an implementation. TI and/or its licensors do not warrant that the design is production worthy. You should" at 6329.01,-943.33 h45
  text "completely validate and test your design implementation to confirm the system functionality for your application." at 6374,-1056 h45
  text ".print_Scale" at 11393.5,-1056.83 h70
  text ".Application_BuildNumber" at 12899,-1056.83 h70
  text "1" at 739.84,-1263.5 h70
  text "2" at 3235.5,-1263.5 h70
  text "3" at 5724.84,-1263.5 h70
  text "4" at 8231.51,-1263.5 h70
  text "5" at 10730.5,-1263.5 h70
  text "6" at 13235.5,-1263.5 h70
M10 Fab Notes:
  drawing of 189 lines, arcs and shapes, not listed
  text "DESIGN INFORMATION" at 12382.02,6356.17 h60
  text "MIN. TRACK WIDTH:" at 11737.46,6224.05 h60
  text "8" at 12833.7,6224.05 h60
  text "MIL" at 12988.46,6224.05 h60
  text "7.874" at 12667.32,6102.36 h60
  text "MIN. CLEARANCE:" at 11737.46,6099.92 h60
  text "MIL" at 12988.46,6099.92 h60
  text "MIN. VIA PAD SIZE:" at 11737.46,5975.8 h60
  text "24" at 12803.71,5975.8 h60
  text "MIL" at 12988.46,5975.8 h60
  text "0.05mm (2MIL)" at 12432.46,5845.9 h60
  text "MINIMUM ANNULAR RING" at 11408.23,5837.67 h60
  text "EXTERNAL" at 13140.46,5837.67 h60
  text "PER" at 11608.23,5727.55 h60
  text "IPC-D-275 CLASS 2 LEVEL C" at 11828.23,5727.54 h60
  text "MIL, HOLES" at 13316.46,5627.07 h60
  text "+/-" at 12924,5618.48 h60
  text "+/-" at 13778,5618.48 h60
  text "REGISTRATION TOLERANCES:" at 11408.23,5617.42 h60
  text "METAL" at 12608,5617.42 h60
  text "5" at 13184.2,5617.42 h60
  text "3" at 14017.2,5617.42 h60
  text "MIL" at 14133.46,5617.42 h60
  text "HOLE SIZE TOLERANCE (UNLESS OTHERWISE SPECIFIED):" at 11408.23,5519.1 h60
  text "+/-" at 13778,5516.23 h60
  text "3" at 14017.2,5515.17 h60
  text "MIL" at 14133.46,5515.17 h60
  text "MATERIAL:" at 11333.46,5377.52 h60
  text "FR-4 High Tg" at 12319.9,5249 h60
  text "X" at 12175.46,5241.01 h60
  text "FR-408" at 11754.46,5236.49 h60
  text "OTHER" at 13242.46,5236.49 h60
  text "62 MIL (1.6mm) +/-10%" at 12074.56,5093.46 h60
  text "X" at 11954.46,5091.01 h60
  text "THICKNESS:" at 11408.23,5085.24 h60
  text "OTHER" at 13359.46,5085.24 h60
  text "TOLERANCE:" at 11408.23,4946.92 h60
  text "X" at 12256.46,4946.92 h60
  text "ANSI IPC-6012 TYPE 3 CLASS 2" at 12434.48,4946.92 h60
  text "OTHER +/-" at 12434.46,4802.73 h60
  text "BOW & TWIST:" at 11408.23,4657.54 h60
  text "X" at 12256.46,4657.54 h60
  text "ANSI IPC-6012 TYPE 3 CLASS 2" at 12434.48,4657.54 h60
  text "OTHER +/-" at 12434.46,4510.85 h60
  text "DRILLING:" at 11333.46,4380.23 h60
  text "NC_DRILL FILES" at 13094.46,4275.04 h60
  text "REFERENCE:" at 11408.23,4271.1 h60
  text "X" at 12065.46,4271.01 h60
  text "AS SHOWN" at 12243.46,4271.1 h60
  text "X" at 12966.46,4271.1 h60
  text "OTHER" at 13392.46,4128.85 h60
  text "PTH COPPER THICKNESS:" at 11407.91,4125.32 h60
  text "X" at 12547.14,4125.32 h60
  text "20-30 um" at 12675.14,4125.32 h60
  text "BOARD FINISH:" at 11333.46,3977.73 h60
  text "SILKSCREEN:" at 11488.68,3867.6 h60
  text "X" at 12446.46,3867.6 h60
  text "TOP" at 12563.46,3867.6 h60
  text "X" at 12956.46,3867.6 h60
  text "BOTTOM" at 13074.46,3867.6 h60
  text "SILKSCREEN COLOR:" at 11488.68,3712.41 h60
  text "X" at 12445.46,3712.41 h60
  text "WHITE" at 12563.46,3712.41 h60
  text "OTHER" at 13074.46,3712.41 h60
  text "X" at 12576.46,3568.96 h60
  text "GREEN" at 12694.46,3568.96 h60
  text "OTHER" at 13312.46,3568.96 h60
  text "SOLDER RESIST COLOR:" at 11488.68,3562.1 h60
  text "X" at 12576.46,3414.71 h60
  text "MATTE" at 12694.46,3414.71 h60
  text "SEMI-GLOSS" at 13312,3414.07 h60
  text "IMMERSION GOLD (ENIG)" at 12394.46,3241.94 h60
  text "ENEPIG" at 13732,3234.72 h60
  text "SURFACE FINISH:" at 11333.46,3233.72 h60
  text "X" at 12216.46,3233.72 h60
  text "IMM. TIN/SILVER OR EQUIV" at 11663,3096.4 h60
  text "OTHER" at 13094.46,3092.47 h60
  text "ARRAY/PANEL:" at 11333.46,2937.09 h60
  text "CUT AND TRIM PER M1 BOARD OUTLINE" at 12394.46,2928.87 h60
  text "N.C. ROUTE" at 12394.46,2792.9 h60
  text "X" at 13082.46,2792.9 h60
  text "V. SCORE" at 13260.46,2792.9 h60
  text "CERTIFICATION:" at 11333.46,2663.77 h60
  text "MATERIALS AND WORKMANSHIP FOR ALL PCBS" at 12058.46,2663.77 h60
  text "TO MEET OR EXCEED THE REQUIREMENTS OF:" at 12058.46,2569.71 h60
  text "X" at 11695.97,2441.08 h60
  text "ANSI IPC-A-600F CLASS ->" at 11823.96,2441.08 h60
  text "X" at 13471.97,2441.08 h60
  text "2" at 13581.96,2441.08 h60
  text "1" at 13266.96,2439.58 h60
  text "3" at 13935.96,2439.58 h60
  text "X" at 12507.97,2293.39 h60
  text "RoHS" at 12635.96,2293.39 h60
  text "OTHER" at 13280.36,2293.39 h60
  text "PER ORDER" at 13677.42,2293.39 h60
  text "ALL BOARDS MUST MEET OR EXCEED UL94-V0 REQUIREMENTS." at 11361,2139.57 h60
  text "PCB MUST BEAR THE UL94V-0 UL REGISTERED MATERIAL ID NUMBER" at 11361,2023.5 h60
  text "ADDITIONAL REQUIREMENTS:" at 11333.46,1854.08 h60
  text "MICROSECTION:" at 11408.23,1746.95 h60
  text "YES" at 12313.96,1746.95 h60
  text "REQUIRED" at 13175.46,1602.62 h60
  text "BARE BOARD ELEC. TEST:" at 11408.23,1599.76 h60
  text "NONE" at 12713.96,1599.76 h60
  text "X" at 13057.46,1599.76 h60
  text "PER ORDER" at 13767.46,1599.76 h60
  text "XX MIL VIAS REQUIRE NON-CONDUCTIVE FILL AND PLANARIZE" at 11576.38,1394.82 h59
  text "XX MIL VIAS REQUIRE CONDUCTIVE FILL AND PLANARIZE" at 11584.38,1290.84 h60
  text "OUTER XX MIL TRACES REQUIRE 50 OHM SINGLE-ENDED IMPEDANCE" at 11583.39,1127.46 h58
  text "LAYER 2 & 3 (INNER LAYERS) XX MIL WIDE, XX MIL SPACE / TRACES REQUIRE 100 OHM DIFFERENTIAL IMPEDANCE" at 11575.39,891.74 h60
  text ".Layer_Name" at 577,-858.49 h60
M11 Gerber Information:
  lines w10: -292,-930.17 6308,-930.17 ; -292,-726.83 6310,-726.83 ; -292,-523.5 -292,-1133.5 3713,-1133.5 6310,-1133.5 6310,-523.5 -291.5,-523.5 -291.5,-1133.5 1284,-1133.5 ; 2173,-1133.5 2173,-523.5 ; 3440,-726.83 3440,-523.5 ; 4280,-726.83 4280,-523.5 ; 4902,-1140 4902,-937.17
  text "ALL ARTWORK VIEWED FROM TOP SIDE" at -228.5,-655.67 h60
  text "BOARD #:" at 2248,-655.67 h60
  text ".PRJ_Number" at 2793.5,-655.67 h60
  text "REV:" at 3638,-655.67 h60
  text ".PCB_Rev" at 3929.5,-655.67 h60
  text "SVN REV:" at 4476,-655.67 h60
  text ".VersionControl_RevNumber" at 4982,-655.67 h60
  text "LAYER NAME =" at -228.5,-858.49 h60
  text "TID #:" at 2248,-859 h60
  text ".TID" at 2793.5,-859 h60
  text "PLOT NAME =" at -228.5,-1064.34 h60
  text ".plot_File_Name" at 577,-1064.34 h60
  text "GENERATED    :" at 2250,-1064.34 h60
  text ".Print_Date" at 3119.5,-1064.34 h60
  text ".Print_Time" at 3848.5,-1064.34 h60
  text "TEXAS INSTRUMENTS" at 5113,-1064.34 h60
M12 Stackup:
  drawing of 191 lines, arcs and shapes, not listed
  text "Layer" at 9821.59,7874.94 h60
  text "Name" at 10231.51,7874.94 h60
  text "Material" at 11161.25,7874.94 h60
  text "Thickness" at 12021.02,7874.94 h60
  text "Constant" at 12670.85,7874.94 h60
  text "Board Layer Stack" at 13240.71,7874.94 h60
  text "Top Overlay" at 10231.51,7754.94 h60
  text "Top Solder" at 10231.51,7634.94 h60
  text "Solder Resist" at 11161.25,7634.94 h60
  text "0.40mil" at 12021.02,7634.94 h60
  text "3.5" at 12670.85,7634.94 h60
  text "1" at 9821.59,7514.94 h60
  text "Top Layer" at 10231.51,7514.94 h60
  text "1.40mil" at 12021.02,7514.94 h60
  text "Dielectric1" at 10231.51,7394.94 h60
  text "FR-4 High Tg" at 11161.25,7394.94 h60
  text "59.20mil" at 12021.02,7394.94 h60
  text "4.8" at 12670.85,7394.94 h60
  text "2" at 9821.59,7274.94 h60
  text "Bottom Layer" at 10231.51,7274.94 h60
  text "1.40mil" at 12021.02,7274.94 h60
  text "Bottom Solder" at 10231.51,7154.94 h60
  text "Solder Resist" at 11161.25,7154.94 h60
  text "0.40mil" at 12021.02,7154.94 h60
  text "3.5" at 12670.85,7154.94 h60
  text "Bottom Overlay" at 10231.51,7034.94 h60
  text ".Layer_Name" at 577,-858.49 h60
M13 Component Bodies Top:
  text ".Layer_Name" at 577,-858.49 h60
M14 Component Bodies Bottom:
  text ".Layer_Name" at 577,-858.49 h60
M15 Courtyards Top:
  text ".Layer_Name" at 577,-858.49 h60
M16 Courtyards Bottom:
  text ".Layer_Name" at 577,-858.49 h60
Drill Drawing:
  circle w10: c5363.72,3290.28 r27.63
  circle w10: c5363.72,3041.64 r16.58
  circle w10: c5363.72,3041.64 r27.63
  lines w10: 5336.09,2696.31 5391.34,2696.31 5363.72,2641.06 5336.09,2696.31 ; 5336.09,2765.38 5391.34,2765.38 5391.34,2820.63 5336.09,2820.63 5336.09,2765.38 ; 5336.09,2903.51 5349.9,2903.51 5363.72,2889.7 5377.53,2903.51 5391.34,2903.51 5377.53,2917.32 5391.34,2931.14 5377.53,2931.14 5363.72,2944.95 5349.9,2931.14 5336.09,2931.14 5349.9,2917.32 5336.09,2903.51 ; 5336.09,3138.34 5391.34,3138.34 5391.34,3193.59 5336.09,3193.59 5336.09,3138.34 ; 5347.14,3149.39 5380.29,3149.39 5380.29,3182.54 5347.14,3182.54 5347.14,3149.39
  lines w12: 5286,2603.76 8517.49,2603.76 ; 5286,3349.68 8517.49,3349.68 ; 5623.86,2479.44 5623.86,3474 ; 5955.86,2479.44 5955.86,3474 ; 6592.43,2479.44 6592.43,3474 ; 6851.57,2479.44 6851.57,3474 ; 7226.72,2479.44 7226.72,3474 ; 7951.05,2479.44 7951.05,3474 ; 5286,2479.44 8517.49,2479.44 8517.49,3474 5286,3474 5286,2479.44
  text "Symbol" at 5360.59,3386.98 h72
  text "Quantity" at 5661.16,3386.98 h72
  text "Finished Hole Size" at 5993.16,3386.98 h72
  text "Plated" at 6629.72,3386.98 h72
  text "Hole Type" at 6888.86,3386.98 h72
  text "Drill Layer Pair" at 7264.02,3386.98 h72
  text "Hole Tolerance" at 7988.35,3386.98 h72
  text "2" at 5661.16,3262.66 h60
  text "10.00mil (0.254mm)" at 5993.16,3262.66 h60
  text "PTH" at 6629.72,3262.66 h60
  text "Round" at 6888.86,3262.66 h60
  text "Top Layer - Bottom Layer" at 7264.02,3262.66 h60
  text "2" at 5661.16,3138.34 h60
  text "31.50mil (0.800mm)" at 5993.16,3138.34 h60
  text "PTH" at 6629.72,3138.34 h60
  text "Round" at 6888.86,3138.34 h60
  text "Top Layer - Bottom Layer" at 7264.02,3138.34 h60
  text "2" at 5661.16,3014.02 h60
  text "35.00mil (0.889mm)" at 5993.16,3014.02 h60
  text "PTH" at 6629.72,3014.02 h60
  text "Round" at 6888.86,3014.02 h60
  text "Top Layer - Bottom Layer" at 7264.02,3014.02 h60
  text "4" at 5661.16,2889.7 h60
  text "35.43mil (0.900mm)" at 5993.16,2889.7 h60
  text "PTH" at 6629.72,2889.7 h60
  text "Round" at 6888.86,2889.7 h60
  text "Top Layer - Bottom Layer" at 7264.02,2889.7 h60
  text "2" at 5661.16,2765.38 h60
  text "43.31mil (1.100mm)" at 5993.16,2765.38 h60
  text "PTH" at 6629.72,2765.38 h60
  text "Round" at 6888.86,2765.38 h60
  text "Top Layer - Bottom Layer" at 7264.02,2765.38 h60
  text "6" at 5661.16,2641.06 h60
  text "63.00mil (1.600mm)" at 5993.16,2641.06 h60
  text "PTH" at 6629.72,2641.06 h60
  text "Round" at 6888.86,2641.06 h60
  text "Top Layer - Bottom Layer" at 7264.02,2641.06 h60
  text "18 Total" at 5661.16,2516.74 h60
  text ".Layer_Name" at 577,-858.49 h60
M17 Embedded Cavity:
  text ".Layer_Name" at 577,-858.49 h60
M18 Embedded Assembly:
  text ".Layer_Name" at 577,-858.49 h60
M19 Embedded Keepout:
  text ".Layer_Name" at 577,-858.49 h60

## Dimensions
0,-39.37 to -10,1328.74 on M2 Board Dimensions
0,-400 to 1000,-400 on M2 Board Dimensions
0,0 to 3149.61,-39.37 on M2 Board Dimensions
